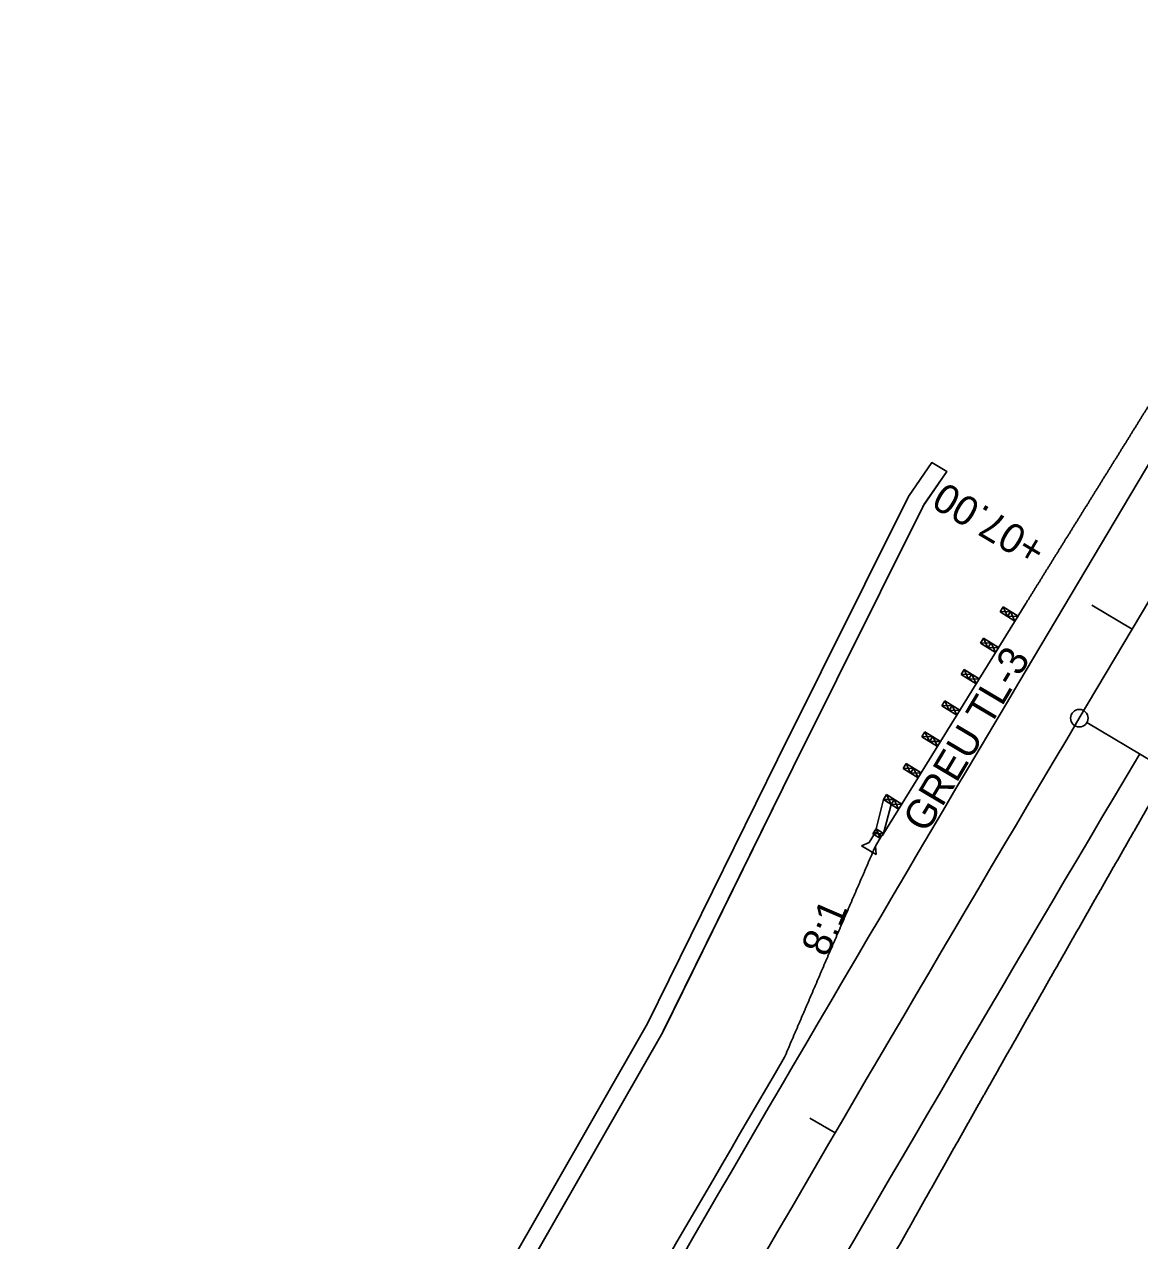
# Model space of a CAD drawing. Extents: x 2138032 to 2141863, y 405316 to 411953.
# Drawn here: x 2140776.6 to 2140967.3, y 410110.4 to 410318.4 of the extents above; entities that cross this region are included whole.
import ezdxf

# ---------------------------------------------------------------- set-up
doc = ezdxf.new("R2010")
doc.units = 0
for name, color, linetype in [('Default', 7, 'Continuous'), ('Prop Dimension Text', 7, 'Continuous'), ('Prop EOT', 7, 'Continuous'), ('Prop Guardrail', 7, 'Continuous'), ('Prop Guardrail Anchor Unit CELL', 7, 'Continuous'), ('Prop Horizontal Alignment', 7, 'Continuous'), ('Prop Horizontal Alignment Station Label', 7, 'Continuous'), ('Prop Horizontal Alignment Tick Large', 7, 'Continuous'), ('Prop Horizontal Alignment Tick Small', 7, 'Continuous'), ('Prop Paved Shoulder', 7, 'Continuous'), ('Prop SS Fill Line', 7, 'Continuous')]:
    doc.layers.add(name, color=color, linetype=linetype)

msp = doc.modelspace()

# ---------------------------------------------------------------- linework, layer by layer
at = {"layer": 'Default'}
msp.add_lwpolyline([(2140779.2, 409947.28), (2140789.36, 409970.23), (2140813.26, 410014.31), (2140836.34, 410058.88), (2140860.81, 410102.57), (2140885.73, 410146.07), (2140908.01, 410191.38), (2140930.41, 410236.37), (2140934.3, 410241.94), (2140931.71, 410243.48), (2140927.72, 410237.7), (2140905.32, 410192.72), (2140883.13, 410147.57), (2140858.2, 410104.03), (2140833.68, 410060.26), (2140810.6, 410015.69), (2140786.72, 409971.66), (2140776.58, 409948.76)], close=True, dxfattribs=at)
at = {"layer": 'Prop EOT'}
msp.add_line((2140946.62, 410205.9), (2141250.61, 410718.06), dxfattribs=at)
for radius in [11112, 11088]:
    msp.add_arc((2150502.22, 404534.29), radius, 149.309258, 150.70339, dxfattribs=at)
at = {"layer": 'Prop Guardrail'}
for points in [[(2140984.07, 410277.81), (2140983.8, 410277.36), (2140983.52, 410276.92), (2140983.24, 410276.47), (2140983.1, 410276.25), (2140982.96, 410276.02), (2140982.83, 410275.8), (2140982.69, 410275.58), (2140982.55, 410275.35), (2140982.41, 410275.13), (2140982.27, 410274.91), (2140982.13, 410274.68), (2140981.99, 410274.46), (2140981.86, 410274.24), (2140981.72, 410274.01), (2140981.58, 410273.79), (2140981.44, 410273.57), (2140981.3, 410273.34), (2140981.16, 410273.12), (2140981.02, 410272.9), (2140980.89, 410272.67), (2140980.75, 410272.45), (2140980.61, 410272.23), (2140980.47, 410272), (2140980.33, 410271.78), (2140980.19, 410271.56), (2140980.05, 410271.33), (2140979.91, 410271.11), (2140979.78, 410270.89), (2140979.64, 410270.66), (2140979.5, 410270.44), (2140979.36, 410270.22), (2140979.22, 410270), (2140979.08, 410269.77), (2140978.94, 410269.55), (2140978.81, 410269.33), (2140978.67, 410269.1), (2140978.53, 410268.88), (2140978.39, 410268.66), (2140978.25, 410268.43), (2140978.11, 410268.21), (2140977.97, 410267.99), (2140977.84, 410267.76), (2140977.7, 410267.54), (2140977.56, 410267.32), (2140977.42, 410267.09), (2140977.28, 410266.87), (2140977.14, 410266.65), (2140977, 410266.42), (2140976.86, 410266.2), (2140976.73, 410265.98), (2140976.59, 410265.75), (2140976.45, 410265.53), (2140976.31, 410265.31), (2140976.17, 410265.08), (2140976.03, 410264.86), (2140975.89, 410264.64), (2140975.76, 410264.41), (2140975.62, 410264.19), (2140975.48, 410263.97), (2140975.34, 410263.74), (2140975.2, 410263.52), (2140975.06, 410263.3), (2140974.92, 410263.07), (2140974.79, 410262.85), (2140974.65, 410262.63), (2140974.51, 410262.4), (2140974.37, 410262.18), (2140974.23, 410261.96), (2140974.09, 410261.73), (2140973.95, 410261.51), (2140973.81, 410261.29), (2140973.68, 410261.06), (2140973.54, 410260.84), (2140973.4, 410260.62), (2140973.26, 410260.39), (2140973.12, 410260.17), (2140972.98, 410259.95), (2140972.84, 410259.72), (2140972.71, 410259.5), (2140972.57, 410259.28), (2140972.43, 410259.05), (2140972.29, 410258.83), (2140972.15, 410258.61), (2140972.01, 410258.38), (2140971.87, 410258.16), (2140971.74, 410257.94), (2140971.6, 410257.71), (2140971.46, 410257.49), (2140971.32, 410257.27), (2140971.18, 410257.04), (2140971.04, 410256.82), (2140970.9, 410256.6), (2140970.76, 410256.38), (2140970.63, 410256.15), (2140970.49, 410255.93), (2140970.35, 410255.71), (2140970.21, 410255.48), (2140970.07, 410255.26), (2140969.93, 410255.04), (2140969.79, 410254.81), (2140969.66, 410254.59), (2140969.52, 410254.37), (2140969.38, 410254.14), (2140969.24, 410253.92), (2140969.1, 410253.7), (2140968.96, 410253.47), (2140968.82, 410253.25), (2140968.69, 410253.03), (2140968.55, 410252.8), (2140968.41, 410252.58), (2140968.27, 410252.36), (2140968.13, 410252.13), (2140967.99, 410251.91), (2140967.85, 410251.69), (2140967.71, 410251.46), (2140967.58, 410251.24), (2140967.44, 410251.02), (2140967.3, 410250.79), (2140967.16, 410250.57), (2140967.02, 410250.35), (2140966.88, 410250.12), (2140966.74, 410249.9), (2140966.61, 410249.68), (2140966.47, 410249.45), (2140966.33, 410249.23), (2140966.19, 410249.01), (2140966.05, 410248.78), (2140965.91, 410248.56), (2140965.77, 410248.34), (2140965.64, 410248.11), (2140965.5, 410247.89), (2140965.36, 410247.67), (2140965.22, 410247.44), (2140965.08, 410247.22), (2140964.94, 410247), (2140964.8, 410246.77), (2140964.67, 410246.55), (2140964.53, 410246.33), (2140964.39, 410246.1), (2140964.25, 410245.88), (2140964.11, 410245.66), (2140963.97, 410245.43), (2140963.83, 410245.21), (2140963.69, 410244.99), (2140963.56, 410244.76), (2140963.42, 410244.54), (2140963.28, 410244.32), (2140963.14, 410244.09), (2140963, 410243.87), (2140962.86, 410243.65), (2140962.72, 410243.43), (2140962.59, 410243.2), (2140962.45, 410242.98), (2140962.31, 410242.76), (2140962.17, 410242.53), (2140962.03, 410242.31), (2140961.89, 410242.09), (2140961.75, 410241.86), (2140961.62, 410241.64), (2140961.48, 410241.42), (2140961.34, 410241.19), (2140961.2, 410240.97), (2140961.06, 410240.75), (2140960.92, 410240.52), (2140960.78, 410240.3), (2140960.64, 410240.08), (2140960.51, 410239.85), (2140960.37, 410239.63), (2140960.23, 410239.41), (2140960.09, 410239.18), (2140959.95, 410238.96), (2140959.81, 410238.74), (2140959.67, 410238.51), (2140959.54, 410238.29), (2140959.4, 410238.07), (2140959.26, 410237.84), (2140959.12, 410237.62), (2140958.98, 410237.4), (2140958.84, 410237.17), (2140958.7, 410236.95), (2140958.57, 410236.73), (2140958.43, 410236.5), (2140958.29, 410236.28), (2140958.15, 410236.06), (2140958.01, 410235.83), (2140957.87, 410235.61), (2140957.73, 410235.39), (2140957.59, 410235.16), (2140957.46, 410234.94), (2140957.32, 410234.72), (2140957.18, 410234.49), (2140957.04, 410234.27), (2140956.9, 410234.05), (2140956.76, 410233.82), (2140956.62, 410233.6), (2140956.49, 410233.38), (2140956.35, 410233.15), (2140956.21, 410232.93), (2140956.07, 410232.71), (2140955.93, 410232.48), (2140955.79, 410232.26), (2140955.65, 410232.04), (2140955.52, 410231.81), (2140955.38, 410231.59), (2140955.24, 410231.37), (2140955.1, 410231.14), (2140954.96, 410230.92), (2140954.82, 410230.7), (2140954.68, 410230.48), (2140954.54, 410230.25), (2140954.41, 410230.03), (2140954.27, 410229.81), (2140954.13, 410229.58), (2140953.99, 410229.36), (2140953.85, 410229.14), (2140953.71, 410228.91), (2140953.57, 410228.69), (2140953.44, 410228.47), (2140953.3, 410228.24)], [(2140953.3, 410228.24), (2140953.16, 410228.02), (2140953.02, 410227.8), (2140952.88, 410227.57), (2140952.74, 410227.35), (2140952.6, 410227.13), (2140952.47, 410226.9), (2140952.33, 410226.68), (2140952.19, 410226.46), (2140952.05, 410226.23), (2140951.91, 410226.01), (2140951.77, 410225.79), (2140951.63, 410225.56), (2140951.49, 410225.34), (2140951.36, 410225.12), (2140951.22, 410224.89), (2140951.08, 410224.67), (2140950.94, 410224.45), (2140950.8, 410224.22), (2140950.66, 410224), (2140950.52, 410223.78), (2140950.39, 410223.55), (2140950.25, 410223.33), (2140950.11, 410223.11), (2140949.97, 410222.88), (2140949.83, 410222.66), (2140949.69, 410222.44), (2140949.55, 410222.21), (2140949.42, 410221.99), (2140949.28, 410221.77), (2140949.14, 410221.54), (2140949, 410221.32), (2140948.86, 410221.1), (2140948.72, 410220.87), (2140948.58, 410220.65), (2140948.44, 410220.43), (2140948.31, 410220.2), (2140948.17, 410219.98), (2140948.03, 410219.76), (2140947.89, 410219.53), (2140947.86, 410219.49), (2140947.83, 410219.44), (2140947.81, 410219.4)]]:
    msp.add_open_spline(points, degree=3, dxfattribs=at)
for points in [[(2140955.02, 410160.66), (2140955.4, 410161.34), (2140955.79, 410162.02), (2140956.17, 410162.7), (2140956.56, 410163.38), (2140956.95, 410164.05), (2140957.33, 410164.73), (2140957.72, 410165.41), (2140958.1, 410166.09), (2140958.49, 410166.77), (2140958.88, 410167.44), (2140959.26, 410168.12), (2140959.65, 410168.8), (2140960.04, 410169.48), (2140960.42, 410170.15), (2140960.81, 410170.83), (2140961.2, 410171.51), (2140961.58, 410172.19), (2140961.97, 410172.86), (2140962.36, 410173.54), (2140962.74, 410174.22), (2140963.13, 410174.9), (2140963.52, 410175.57), (2140963.9, 410176.25), (2140964.29, 410176.93), (2140964.68, 410177.61), (2140965.06, 410178.28), (2140965.45, 410178.96), (2140965.84, 410179.64), (2140966.23, 410180.31), (2140966.61, 410180.99), (2140967, 410181.67), (2140967.39, 410182.35), (2140967.77, 410183.02), (2140968.16, 410183.7), (2140968.55, 410184.38), (2140968.94, 410185.05), (2140969.32, 410185.73), (2140969.71, 410186.41), (2140970.1, 410187.09), (2140970.49, 410187.76), (2140970.88, 410188.44), (2140971.26, 410189.12), (2140971.65, 410189.79), (2140972.04, 410190.47), (2140972.43, 410191.15), (2140972.82, 410191.82), (2140973.2, 410192.5), (2140973.59, 410193.18), (2140973.98, 410193.86), (2140974.37, 410194.54), (2140974.76, 410195.21), (2140975.15, 410195.89), (2140975.54, 410196.57), (2140975.92, 410197.25), (2140976.31, 410197.93), (2140976.7, 410198.6), (2140977.09, 410199.28), (2140977.48, 410199.96), (2140977.87, 410200.64), (2140978.26, 410201.31), (2140978.64, 410201.99), (2140979.03, 410202.67), (2140979.42, 410203.35), (2140979.81, 410204.03), (2140980.2, 410204.7), (2140980.59, 410205.38), (2140980.98, 410206.06), (2140981.36, 410206.74), (2140981.75, 410207.42), (2140982.14, 410208.09), (2140982.53, 410208.77), (2140982.92, 410209.45), (2140983.31, 410210.13), (2140983.7, 410210.8)], [(2140926.6, 410110.42), (2140926.98, 410111.1), (2140927.36, 410111.78), (2140927.75, 410112.46), (2140928.13, 410113.14), (2140928.51, 410113.82), (2140928.89, 410114.5), (2140929.28, 410115.18), (2140929.66, 410115.86), (2140930.04, 410116.54), (2140930.42, 410117.22), (2140930.81, 410117.9), (2140931.19, 410118.58), (2140931.57, 410119.26), (2140931.95, 410119.94), (2140932.34, 410120.62), (2140932.72, 410121.3), (2140933.1, 410121.98), (2140933.49, 410122.66), (2140933.87, 410123.34), (2140934.25, 410124.02), (2140934.64, 410124.7), (2140935.02, 410125.37), (2140935.4, 410126.05), (2140935.79, 410126.73), (2140936.17, 410127.41), (2140936.55, 410128.09), (2140936.94, 410128.77), (2140937.32, 410129.45), (2140937.7, 410130.13), (2140938.09, 410130.81), (2140938.47, 410131.49), (2140938.85, 410132.17), (2140939.24, 410132.85), (2140939.62, 410133.53), (2140940.01, 410134.2), (2140940.39, 410134.88), (2140940.77, 410135.56), (2140941.16, 410136.24), (2140941.54, 410136.92), (2140941.93, 410137.6), (2140942.31, 410138.28), (2140942.7, 410138.96), (2140943.08, 410139.64), (2140943.46, 410140.31), (2140943.85, 410140.99), (2140944.23, 410141.67), (2140944.62, 410142.35), (2140945, 410143.03), (2140945.39, 410143.71), (2140945.77, 410144.39), (2140946.16, 410145.06), (2140946.54, 410145.74), (2140946.93, 410146.42), (2140947.31, 410147.1), (2140947.69, 410147.78), (2140948.08, 410148.46), (2140948.46, 410149.14), (2140948.85, 410149.81), (2140949.23, 410150.49), (2140949.62, 410151.17), (2140950.01, 410151.85), (2140950.39, 410152.53), (2140950.78, 410153.21), (2140951.16, 410153.88), (2140951.55, 410154.56), (2140951.93, 410155.24), (2140952.32, 410155.92), (2140952.7, 410156.6), (2140953.09, 410157.27), (2140953.47, 410157.95), (2140953.86, 410158.63), (2140954.25, 410159.31), (2140954.63, 410159.99), (2140955.02, 410160.66)], [(2140898.44, 410060.04), (2140898.82, 410060.72), (2140899.2, 410061.4), (2140899.58, 410062.08), (2140899.96, 410062.77), (2140900.34, 410063.45), (2140900.72, 410064.13), (2140901.1, 410064.81), (2140901.48, 410065.49), (2140901.85, 410066.17), (2140902.23, 410066.86), (2140902.61, 410067.54), (2140902.99, 410068.22), (2140903.37, 410068.9), (2140903.75, 410069.58), (2140904.13, 410070.26), (2140904.51, 410070.94), (2140904.89, 410071.63), (2140905.27, 410072.31), (2140905.65, 410072.99), (2140906.03, 410073.67), (2140906.41, 410074.35), (2140906.79, 410075.03), (2140907.17, 410075.71), (2140907.55, 410076.4), (2140907.93, 410077.08), (2140908.31, 410077.76), (2140908.69, 410078.44), (2140909.07, 410079.12), (2140909.45, 410079.8), (2140909.83, 410080.48), (2140910.21, 410081.16), (2140910.59, 410081.84), (2140910.97, 410082.52), (2140911.35, 410083.21), (2140911.73, 410083.89), (2140912.11, 410084.57), (2140912.49, 410085.25), (2140912.87, 410085.93), (2140913.25, 410086.61), (2140913.63, 410087.29), (2140914.01, 410087.97), (2140914.39, 410088.65), (2140914.77, 410089.33), (2140915.15, 410090.01), (2140915.53, 410090.69), (2140915.91, 410091.38), (2140916.3, 410092.06), (2140916.68, 410092.74), (2140917.06, 410093.42), (2140917.44, 410094.1), (2140917.82, 410094.78), (2140918.2, 410095.46), (2140918.58, 410096.14), (2140918.96, 410096.82), (2140919.34, 410097.5), (2140919.73, 410098.18), (2140920.11, 410098.86), (2140920.49, 410099.54), (2140920.87, 410100.22), (2140921.25, 410100.9), (2140921.63, 410101.58), (2140922.01, 410102.26), (2140922.4, 410102.94), (2140922.78, 410103.62), (2140923.16, 410104.3), (2140923.54, 410104.98), (2140923.92, 410105.66), (2140924.31, 410106.34), (2140924.69, 410107.02), (2140925.07, 410107.7), (2140925.45, 410108.38), (2140925.83, 410109.06), (2140926.22, 410109.74), (2140926.6, 410110.42)]]:
    msp.add_spline(points, degree=3, dxfattribs=at)
at = {"layer": 'Prop Guardrail Anchor Unit CELL'}
for p, q in [((2140947.81, 410219.4), (2140923.21, 410179.64)), ((2140943.92, 410218.82), (2140943.39, 410217.97)), ((2140943.39, 410217.97), (2140945.19, 410218.03)), ((2140945.94, 410216.39), (2140943.39, 410217.97)), ((2140946.47, 410217.24), (2140943.92, 410218.82)), ((2140944.67, 410217.18), (2140943.92, 410218.82)), ((2140945.19, 410218.03), (2140944.67, 410217.18)), ((2140945.19, 410218.03), (2140945.94, 410216.39)), ((2140944.67, 410217.18), (2140946.47, 410217.24)), ((2140945.94, 410216.39), (2140944.67, 410217.18)), ((2140946.47, 410217.24), (2140945.94, 410216.39)), ((2140940.56, 410213.48), (2140940.03, 410212.63)), ((2140940.03, 410212.63), (2140941.86, 410212.68)), ((2140942.63, 410211.03), (2140940.03, 410212.63)), ((2140943.15, 410211.88), (2140940.56, 410213.48)), ((2140941.33, 410211.83), (2140940.56, 410213.48)), ((2140941.86, 410212.68), (2140941.33, 410211.83)), ((2140943.15, 410211.88), (2140941.33, 410211.83)), ((2140941.86, 410212.68), (2140942.63, 410211.03)), ((2140937.25, 410208.12), (2140936.72, 410207.27)), ((2140939.84, 410206.52), (2140937.25, 410208.12)), ((2140938.02, 410206.47), (2140937.25, 410208.12)), ((2140936.72, 410207.27), (2140938.54, 410207.32)), ((2140939.31, 410205.67), (2140936.72, 410207.27)), ((2140938.54, 410207.32), (2140938.02, 410206.47)), ((2140939.84, 410206.52), (2140938.02, 410206.47)), ((2140938.54, 410207.32), (2140939.31, 410205.67)), ((2140933.94, 410202.76), (2140933.42, 410201.91)), ((2140933.42, 410201.91), (2140935.23, 410201.96)), ((2140936, 410200.31), (2140933.42, 410201.91)), ((2140936.52, 410201.16), (2140933.94, 410202.76)), ((2140934.71, 410201.11), (2140933.94, 410202.76)), ((2140935.23, 410201.96), (2140934.71, 410201.11)), ((2140935.23, 410201.96), (2140936, 410200.31)), ((2140936.52, 410201.16), (2140934.71, 410201.11)), ((2140936.52, 410201.16), (2140936, 410200.31)), ((2140930.54, 410197.45), (2140930.02, 410196.6)), ((2140933.21, 410195.8), (2140930.54, 410197.45)), ((2140931.35, 410195.78), (2140930.54, 410197.45)), ((2140930.02, 410196.6), (2140931.88, 410196.63)), ((2140932.68, 410194.95), (2140930.02, 410196.6)), ((2140931.88, 410196.63), (2140931.35, 410195.78)), ((2140933.21, 410195.8), (2140931.35, 410195.78)), ((2140931.88, 410196.63), (2140932.68, 410194.95)), ((2140927.34, 410192.02), (2140926.82, 410191.17)), ((2140926.82, 410191.17), (2140928.62, 410191.23)), ((2140929.37, 410189.59), (2140926.82, 410191.17)), ((2140929.89, 410190.44), (2140927.34, 410192.02)), ((2140928.09, 410190.38), (2140927.34, 410192.02)), ((2140928.62, 410191.23), (2140928.09, 410190.38)), ((2140928.62, 410191.23), (2140929.37, 410189.59)), ((2140929.89, 410190.44), (2140928.09, 410190.38)), ((2140923.45, 410185.85), (2140922.2, 410180.86)), ((2140923.97, 410186.7), (2140923.45, 410185.85)), ((2140923.45, 410185.85), (2140925.28, 410185.89)), ((2140926.05, 410184.23), (2140923.45, 410185.85)), ((2140924.75, 410185.04), (2140923.48, 410180.07)), ((2140926.58, 410185.09), (2140923.97, 410186.7)), ((2140924.75, 410185.04), (2140923.97, 410186.7)), ((2140925.28, 410185.89), (2140924.75, 410185.04)), ((2140926.58, 410185.09), (2140924.75, 410185.04)), ((2140925.28, 410185.89), (2140926.05, 410184.23)), ((2140922.2, 410180.86), (2140921.67, 410180.01)), ((2140922.2, 410180.86), (2140921.94, 410180.43)), ((2140923.48, 410180.07), (2140922.2, 410180.86)), ((2140922.95, 410179.22), (2140922.2, 410180.86)), ((2140919.7, 410177.94), (2140921.04, 410178.52)), ((2140921.04, 410178.52), (2140922.08, 410180.28)), ((2140921.67, 410180.01), (2140923.48, 410180.07)), ((2140922.95, 410179.22), (2140921.67, 410180.01)), ((2140922.08, 410180.28), (2140922.61, 410179.97)), ((2140923.13, 410179.65), (2140922.09, 410177.89)), ((2140922.61, 410179.97), (2140923.13, 410179.65)), ((2140922.23, 410176.44), (2140919.7, 410177.94)), ((2140922.09, 410177.89), (2140922.23, 410176.44))]:
    msp.add_line(p, q, dxfattribs=at)
at = {"layer": 'Prop Horizontal Alignment'}
msp.add_line((2140956.94, 410199.77), (2141260.93, 410711.93), dxfattribs=at)
msp.add_arc((2150502.22, 404534.29), 11100, 149.309258, 150.70339, dxfattribs=at)
at = {"layer": 'Prop Horizontal Alignment Station Label'}
msp.add_line((2140958.23, 410199.01), (2141164.54, 410076.55), dxfattribs=at)
msp.add_circle((2140956.94, 410199.77), 1.5, dxfattribs=at)
at = {"layer": 'Prop Horizontal Alignment Tick Large'}
msp.add_line((2140965.98, 410215), (2140959.1, 410219.08), dxfattribs=at)
at = {"layer": 'Prop Horizontal Alignment Tick Small'}
msp.add_line((2140915.2, 410128.85), (2140910.88, 410131.37), dxfattribs=at)
at = {"layer": 'Prop Paved Shoulder'}
msp.add_arc((2150502.22, 404534.29), 11114, 149.698996, 150.70339, dxfattribs=at)
msp.add_spline([(2140906.54, 410141.78), (2140906.75, 410142.26), (2140906.96, 410142.75), (2140907.17, 410143.24), (2140907.38, 410143.73), (2140907.58, 410144.22), (2140907.79, 410144.71), (2140908, 410145.19), (2140908.21, 410145.68), (2140908.42, 410146.17), (2140908.63, 410146.66), (2140908.84, 410147.15), (2140909.05, 410147.64), (2140909.26, 410148.12), (2140909.47, 410148.61), (2140909.68, 410149.1), (2140909.89, 410149.59), (2140910.1, 410150.08), (2140910.31, 410150.56), (2140910.52, 410151.05), (2140910.73, 410151.54), (2140910.94, 410152.03), (2140911.15, 410152.52), (2140911.36, 410153.01), (2140911.57, 410153.49), (2140911.78, 410153.98), (2140911.99, 410154.47), (2140912.2, 410154.96), (2140912.41, 410155.45), (2140912.61, 410155.93), (2140912.82, 410156.42), (2140913.03, 410156.91), (2140913.24, 410157.4), (2140913.45, 410157.89), (2140913.66, 410158.37), (2140913.87, 410158.86), (2140914.08, 410159.35), (2140914.29, 410159.84), (2140914.5, 410160.33), (2140914.72, 410160.81), (2140914.93, 410161.3), (2140915.14, 410161.79), (2140915.35, 410162.28), (2140915.56, 410162.77), (2140915.77, 410163.26), (2140915.98, 410163.74), (2140916.19, 410164.23), (2140916.4, 410164.72), (2140916.61, 410165.21), (2140916.82, 410165.7), (2140917.03, 410166.18), (2140917.24, 410166.67), (2140917.45, 410167.16), (2140917.66, 410167.65), (2140917.87, 410168.13), (2140918.08, 410168.62), (2140918.29, 410169.11), (2140918.5, 410169.6), (2140918.71, 410170.09), (2140918.92, 410170.57), (2140919.13, 410171.06), (2140919.34, 410171.55), (2140919.55, 410172.04), (2140919.77, 410172.53), (2140919.98, 410173.01), (2140920.19, 410173.5), (2140920.4, 410173.99), (2140920.61, 410174.48), (2140920.82, 410174.97), (2140921.03, 410175.45), (2140921.24, 410175.94), (2140921.45, 410176.43), (2140921.66, 410176.92), (2140922.08, 410177.89)], degree=3, dxfattribs=at)
at = {"layer": 'Prop SS Fill Line'}
for p, q in [((2140930.19, 410236), (2140934.3, 410241.94)), ((2140908.01, 410191.38), (2140930.41, 410236.37)), ((2140885.82, 410146.24), (2140908.01, 410191.4)), ((2140860.8, 410102.54), (2140885.73, 410146.07))]:
    msp.add_line(p, q, dxfattribs=at)

# ---------------------------------------------------------------- texts
at = {"layer": 'Prop Dimension Text'}
for s, rotation, p in [('+07.00', 149.3093, (2140951.69, 410229.78)), ('8:1', 66.717, (2140913.82, 410158.73))]:
    msp.add_text(s, height=5, rotation=rotation, dxfattribs=at).set_placement(p)
at = {"layer": 'Prop Guardrail Anchor Unit CELL'}
msp.add_text('GREU TL-3', height=5, rotation=59.3093, dxfattribs=at).set_placement((2140930.82, 410179.94))

doc.saveas('drawing.dxf')
